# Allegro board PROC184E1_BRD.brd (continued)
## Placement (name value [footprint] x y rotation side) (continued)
R325  0E  [RES0402_0-5]  20.24 91.07 180 top
R326  0E  [RES0402_0-5]  22.35 91.07 180 top
R327  10K_1%  [RES0201_0-5]  55.1 90.96 0 top
R328  10K_1%  [RES0201_0-5]  55.1 89.95 0 top
R329  0E  [RES0402_0-5]  20.24 89.92 180 top
R330  0E  [RES0402_0-5]  22.35 89.92 180 top
R331  10K_1%  [RES0402_0-5]  101.01 89.75 270 top
R332  0E  [RES0201_0-5]  79.02 89.45 90 top
R333  0E  [RES0201_0-5]  81.99 89.45 90 top
R334  0E  [RES0201_0-5]  82.98 89.45 90 top
R335  0E  [RES0201_0-5]  83.98 89.45 90 top
R336  10K_1%  [RES0402_0-5]  99.42 89.43 0 top
R337  10K_1%  [RES0402_0-5]  73.41 89.36 180 top
R338  0.01E_1%  [RES_FC4L16_0306-4_0-7]  189.83 89.43 90 top
R339  10K_1%  [RES0201_0-5]  55.1 88.86 0 top
R340  0E  [RES0402_0-5]  20.24 88.78 180 top
R341  0E  [RES0402_0-5]  22.35 88.78 180 top
R342  1K_1%  [RES0402_0-5]  76.34 88.6 0 top
R343  0E  [RES0402_0-5]  7.37 88.3 180 top
R344  100E_1%  [RES0402_0-5]  87.52 88.19 0 top
R345  0E  [RES0201_0-5]  42.67 87.88 270 top
R346  22E_1%  [RES0402_0-5]  55.15 87.73 0 top
R347  0E  [RES0402_0-5]  20.24 87.64 180 top
R348  0E  [RES0402_0-5]  22.35 87.64 180 top
R349  100E_1%  [RES0402_0-5]  74.35 86.87 0 top
R350  0E  [RES0402_0-5]  7.37 87.15 180 top
R351  0.01E_1%  [RES_FC4L16_0306-4_0-7]  76.81 87.15 90 top
R352  0.01E_1%  [RES_FC4L16_0306-4_0-7]  169.6 87.03 270 top
R353  10K_1%  [RES0402_0-5]  97.34 86.65 0 top
R354  0E  [RES0402_0-5]  20.24 86.49 0 top
R355  10E_1%  [RES0402_0-5]  22.35 86.49 180 top
R356  100E_1%  [RES0402_0-5]  7.37 85.92 0 top
R357  0.01E_1%  [RES_KRL2012_0805-4_0-7_TI]  227.59 85.58 180 top
R358  10K_1%  [RES0402_0-5]  97.37 85.55 180 top
R359  10E_1%  [RES0402_0-5]  190.58 83.26 180 top
R360  4.7K  [RES0402_0-5]  20.24 85.35 180 top
R361  4.7K  [RES0402_0-5]  7.37 84.78 180 top
R362  0.01E_1%  [RES_FC4L16_0306-4_0-7]  183.68 84.71 0 top
R363  0E  [RES0201_0-5]  80.01 84.6 270 top
R364  0E  [RES0201_0-5]  81 84.6 270 top
R365  0E  [RES0201_0-5]  81.99 84.6 270 top
R366  0E  [RES0201_0-5]  82.98 84.6 270 top
R367  0E  [RES0201_0-5]  83.98 84.6 270 top
R368  0E  [RES0402_0-5]  101.2 68.44 180 top
R369  0.01E_1%  [RES_FC4L16_0306-4_0-7]  167.57 84.49 180 top
R370  10E_1%  [RES0402_0-5]  190.58 82.11 180 top
R371  0E  [RES0402_0-5]  20.24 84.21 180 top
R372  22E_1%  [RES0402_0-5]  22.35 84.21 180 top
R373  0E  [RES0402_0-5]  7.37 83.64 0 top
R374  10E_1%  [RES0402_0-5]  20.24 83.07 180 top
R375  10E_1%  [RES0402_0-5]  22.35 83.07 180 top
R376  0E  [RES0402_0-5]  7.37 82.49 0 top
R377  0.01E_1%  [RES_FC4L16_0306-4_0-7]  87.83 82.41 180 top
R378  0E  [RES0201_0-5]  165.12 82.39 0 top
R379  0E  [RES0402_0-5]  69.65 82.1 180 top
R380  100E_1%  [RES0402_0-5]  20.24 81.92 180 top
R381  4.7K  [RES0402_0-5]  22.35 81.92 0 top
R382  0.01E_1%  [RES_FC4L16_0306-4_0-7]  76.61 81.52 180 top
R383  22E_1%  [RES0402_0-5]  7.37 81.35 180 top
R384  0E  [RES0402_0-5]  69.65 81.06 180 top
R385  0E  [RES0402_0-5]  71.69 81.04 180 top
R387  100E_1%  [RES0402_0-5]  20.24 80.78 180 top
R388  10E_1%  [RES0402_0-5]  190.58 79.22 180 top
R389  22E_1%  [RES0402_0-5]  7.37 80.21 180 top
R392  0E  [RES0402_0-5]  74.13 79.82 180 top
R393  10E_1%  [RES0402_0-5]  190.58 78.08 180 top
R394  4.7K  [RES0402_0-5]  7.38 79.06 180 top
R395  0E  [RES0402_0-5]  116.16 60.29 270 top
R396  240E_1%  [RES0201_0-5]  165.12 78.84 0 top
R398  0E  [RES0402_0-5]  184.83 78.57 180 top
R399  0E  [RES0402_0-5]  115.76 60.7 180 top
R401  10K_1%  [RES0402_0-5]  80.97 77.8 0 top
R402  0E  [RES0402_0-5]  117.97 61.49 0 top
R403  10K_1%  [RES0402_0-5]  41.48 77.7 0 top
R404  0E  [RES0201_0-5]  165.12 76.8 0 top
R405  10K_1%  [RES0402_0-5]  41.5 76.51 180 top
R406  24.9K_1%  [RES0402_0-5]  82.77 76.46 0 top
R407  10K_1%  [RES0402_0-5]  85.35 76.5 90 top
R408  10E_1%  [RES0402_0-5]  190.58 75.19 180 top
R409  10K_1%  [RES0402_0-5]  75.5 75.85 0 top
R410  53.6K_1%  [RES0402_0-5]  81.15 75.83 270 top
R411  10K_1%  [RES0402_0-5]  41.47 75.19 0 top
R412  10E_1%  [RES0402_0-5]  190.58 74.05 180 top
R413  10K_1%  [RES0402_0-5]  75.5 74.58 180 top
R414  1K_1%  [RES0201_0-5]  65.04 73.13 180 top
R415  0.01E_1%  [RES_FC4L16_0306-4_0-7]  82.39 72.86 180 top
R416  0E  [RES0402_0-5]  66.76 72.71 90 top
R417  10K_1%  [RES0402_0-5]  73 72.4 180 top
R418  0.01E_1%  [RES_KRL2012_0805-4_0-7_TI]  232.34 72.17 270 top
R419  10K_1%  [RES0402_0-5]  63.15 72.12 180 top
R420  10K_1%  [RES0402_0-5]  65.13 72.12 180 top
R421  0E  [RES0402_0-5]  84.18 71.87 270 top
R422  10K_1%  [RES0402_0-5]  63.15 70.85 180 top
R423  10K_1%  [RES0402_0-5]  65.13 70.85 180 top
R424  0E  [RES0402_0-5]  82.64 70.67 0 top
R425  0E  [RES0402_0-5]  87.13 70.67 0 top
R426  0E  [RES0402_0-5]  89.02 70.67 180 top
R427  0.01E_1%  [RES_FC4L16_0306-4_0-7]  187.51 70.52 180 top
R428  1K_1%  [RES0201_0-5]  66.23 69.5 180 top
R429  0.01E_1%  [RES_FC4L16_0306-4_0-7]  166.71 69.19 0 top
R430  1K_1%  [RES0402_0-5]  46.31 68.18 0 top
R431  10K  [RES0402_0-5]  58.84 68.18 180 top
R432  0.01E_1%  [RES_FC4L16_0306-4_0-7]  85.66 67.97 180 top
R433  220E_1%  [RES0402_0-5]  187.26 67.5 180 top
R435  1K_1%  [RES0402_0-5]  46.31 66.91 0 top
R436  10K  [RES0402_0-5]  58.84 66.91 180 top
R437  10K_1%  [RES0402_0-5]  79.78 66.33 0 top
R438  0E  [RES0402_0-5]  86.88 65.98 270 top
R439  0.01E_1%  [RES_FC4L16_0306-4_0-7]  166.5 65.97 270 top
R440  240E  [RES0402_0-5]  91.41 65.82 180 top
R441  1K_1%  [RES0402_0-5]  46.31 65.64 0 top
R442  10K  [RES0402_0-5]  58.84 65.64 180 top
R443  10K  [RES0402_0-5]  189.54 65.45 270 top
R444  240E  [RES0402_0-5]  93.01 65.39 90 top
R445  2.2K  [RES0201_0-5]  28.57 65.39 270 top
R446  0E  [RES0402_0-5]  136.61 51.79 0 bottom
R447  10K_1%  [RES0402_0-5]  75.75 64.1 270 top
R448  10K_1%  [RES0402_0-5]  166.57 64.39 180 top
R449  0.008E_1%  [RES1206_0-75]  230.72 64.52 90 top
R450  1K_1%  [RES0402_0-5]  46.31 64.37 0 top
R451  10K  [RES0402_0-5]  58.84 64.37 180 top
R452  0E  [RES0402_0-5]  86.9 64.17 90 top
R453  10K  [RES0402_0-5]  194.62 63.33 0 top
R454  1K_1%  [RES0402_0-5]  46.31 63.1 0 top
R455  10K  [RES0402_0-5]  58.84 63.1 180 top
R456  2.2K  [RES0201_0-5]  25.89 63 90 top
R457  100K  [RES0402_0-5]  143.49 45.92 180 top
R458  0E  [RES0402_0-5]  129.93 62.03 270 top
R459  10K  [RES0402_0-5]  194.62 62.19 180 top
R460  1K_1%  [RES0402_0-5]  46.31 61.83 0 top
R461  10K  [RES0402_0-5]  58.84 61.83 180 top
R462  0E  [RES0402_0-5]  29.9 61.75 270 top
R463  2.2K  [RES0201_0-5]  25.89 61.37 270 top
R464  10E_1%  [RES0402_0-5]  209.06 61.17 180 top
R465  90.9K_1%  [RES0402_0-5]  202.26 61.11 270 top
R466  10K_1%  [RES0402_0-5]  203.49 61.11 90 top
R467  1K_1%  [RES0402_0-5]  46.31 60.56 0 top
R468  10K  [RES0402_0-5]  58.84 60.56 180 top
R469  10K  [RES0402_0-5]  187.33 60.12 270 top
R470  2.2K  [RES0201_0-5]  94.22 24.59 270 top
R471  0E  [RES0402_0-5]  197.25 59.78 180 top
R472  10K_1%  [RES0402_0-5]  191.87 99.63 270 top
R473  24.9K_1%  [RES0402_0-5]  202.47 59.42 180 top
R474  1K_1%  [RES0402_0-5]  46.31 59.29 0 top
R475  10K  [RES0402_0-5]  58.84 59.29 180 top
R476  10K_1%  [RES0402_0-5]  22.4 59.13 90 top
R477  0E  [RES0402_0-5]  127.08 63.6 0 top
R478  2.2K  [RES0201_0-5]  27.07 58.94 90 top
R479  10K_1%  [RES0402_0-5]  193.14 99.63 270 top
R481  10K  [RES0402_0-5]  202.19 55.35 180 top
R482  0E  [RES0402_0-5]  210.75 55.2 0 top
R483  1K_1%  [RES0402_0-5]  46.31 54.63 0 top
R484  10K  [RES0402_0-5]  58.84 54.63 180 top
R485  0.01E_1%  [RES_FC4L16_0306-4_0-7]  154.95 54.31 0 top
R486  5.36K_1%  [RES0402_0-5]  179.41 54.26 270 top
R487  0E  [RES0402_0-5]  180.87 54.97 270 top
R488  0E  [RES0402_0-5]  210.75 54.06 0 top
R489  10K_1%  [RES0402_0-5]  129.6 40.82 270 bottom
R490  10K_1%  [RES0402_0-5]  128.6 40.82 270 bottom
R491  10K_1%  [RES0402_0-5]  127.6 40.82 270 bottom
R492  44.2K_1%  [RES0402_0-5]  207.01 53.56 270 top
R493  10K_1%  [RES0402_0-5]  121.85 40.82 270 bottom
R494  10K_1%  [RES0402_0-5]  120.85 40.82 270 bottom
R495  10K_1%  [RES0402_0-5]  119.85 40.82 270 bottom
R496  1K_1%  [RES0402_0-5]  46.31 53.36 0 top
R497  10K  [RES0402_0-5]  58.84 53.36 180 top
R498  10K_1%  [RES0402_0-5]  200.1 100.31 90 top
R499  10K_1%  [RES0402_0-5]  198.83 100.31 90 top
R500  10K_1%  [RES0402_0-5]  125.6 38.98 90 bottom
R501  10K  [RES0402_0-5]  211.65 52.26 180 top
R502  1K_1%  [RES0402_0-5]  46.31 52.09 0 top
R503  10K  [RES0402_0-5]  58.84 52.09 180 top
R504  10K_1%  [RES0402_0-5]  166.28 52.05 0 top
R505  56.2K_1%  [RES0402_0-5]  156.52 51.85 90 top
R506  10K_1%  [RES0402_0-5]  129.02 39.4 180 bottom
R507  10K_1%  [RES0402_0-5]  121.85 38.82 270 bottom
R508  10K_1%  [RES0402_0-5]  119.85 38.82 270 bottom
R509  10E_1%  [RES0402_0-5]  187 51.51 180 top
R510  10K  [RES0402_0-5]  211.65 51.11 180 top
R511  10K_1%  [RES0402_0-5]  161.51 51.07 270 top
R512  0E  [RES0402_0-5]  166.3 50.96 0 top
R513  10K_1%  [RES0402_0-5]  126.6 39.82 270 bottom
R514  1K_1%  [RES0402_0-5]  46.31 50.82 0 top
R515  10K  [RES0402_0-5]  58.84 50.82 180 top
R516  10K_1%  [RES0402_0-5]  117.85 38.82 270 bottom
R517  10K_1%  [RES0402_0-5]  127.6 38.98 90 bottom
R518  10K_1%  [RES0402_0-5]  120.85 38.82 270 bottom
R519  10K_1%  [RES0402_0-5]  122.27 37.4 180 bottom
R520  10E_1%  [RES0402_0-5]  187 50.37 180 top
R521  24.9K_1%  [RES0402_0-5]  156.02 50.32 180 top
R522  200K  [RES0402_0-5]  203.16 50.32 270 top
R523  10K_1%  [RES0402_0-5]  126.6 37.98 90 bottom
R524  16.2K_1%  [RES0402_0-5]  166.3 49.87 0 top
R525  10K_1%  [RES0201_0-5]  129.93 37.4 0 bottom
R526  22E_1%  [RES0402_0-5]  128.18 37.4 180 bottom
R527  10K_1%  [RES0402_0-5]  118.43 37.4 0 bottom
R528  0E  [RES0402_0-5]  174.38 49.56 0 top
R529  1K_1%  [RES0402_0-5]  46.31 49.55 0 top
R530  10K  [RES0402_0-5]  58.84 49.55 180 top
R531  10K_1%  [RES0402_0-5]  173.06 49.19 90 top
R532  22E_1%  [RES0402_0-5]  120.99 36.81 270 bottom
R533  100K  [RES0402_0-5]  122.27 36.4 0 bottom
R534  10K_1%  [RES0402_0-5]  159.95 48.64 270 top
R536  1K_1%  [RES0402_0-5]  46.31 48.28 0 top
R537  10K  [RES0402_0-5]  58.84 48.28 180 top
R538  10K_1%  [RES0402_0-5]  182.89 48.19 270 top
R539  0E  [RES0402_0-5]  221.12 47.8 90 top
R540  100K  [RES0402_0-5]  121.41 35.42 0 bottom
R541  10K_1%  [RES0201_0-5]  125.27 35.4 180 bottom
R542  10K_1%  [RES0402_0-5]  128.18 35.4 180 bottom
R543  100K  [RES0402_0-5]  129.6 35.98 270 bottom
R544  49.9E_1%  [RES0402_0-5]  162.8 47.31 90 top
R545  10K_1%  [RES0402_0-5]  176.67 47.09 90 top
R546  0E  [RES0402_0-5]  178.82 47.05 270 top
R547  10K_1%  [RES0402_0-5]  181.29 53.42 0 top
R548  1K_1%  [RES0402_0-5]  46.31 47.01 0 top
R549  10K  [RES0402_0-5]  58.84 47.01 180 top
R550  10K_1%  [RES0201_0-5]  65.74 46.79 180 top
R551  10E_1%  [RES0402_0-5]  187 46.75 180 top
R552  1K_1%  [RES0402_0-5]  128.18 36.4 180 bottom
R553  1K_1%  [RES0402_0-5]  46.31 45.74 0 top
R554  10K  [RES0402_0-5]  58.84 45.74 180 top
R555  10E_1%  [RES0402_0-5]  187 45.61 180 top
R556  49.9E_1%  [RES0402_0-5]  78.55 45.43 90 top
R557  10K_1%  [RES0402_0-5]  159.21 43.39 180 top
R558  10E_1%  [RES0402_0-5]  187 42.56 180 top
R559  0E  [RES0402_0-5]  51.77 42.54 270 top
R560  4.7K  [RES0402_0-5]  59.67 42.2 0 top
R561  10K  [RES0402_0-5]  74.5 41.83 180 top
R562  10E_1%  [RES0402_0-5]  187 41.42 180 top
R563  10K  [RES0402_0-5]  90.48 41.36 90 top
R564  10K_1%  [RES0402_0-5]  53.78 40.8 0 top
R565  0E  [RES0402_0-5]  51.77 40.63 90 top
R566  1M_1%  [RES0402_0-5]  79.79 40.6 180 top
R567  10K  [RES0402_0-5]  74.5 40.56 0 top
R568  0E  [RES0402_0-5]  228.74 40.47 180 top
R569  10K_1%  [RES0402_0-5]  79.79 39.45 0 top
R570  10E_1%  [RES0402_0-5]  169.26 39.25 90 top
R571  10E_1%  [RES0402_0-5]  170.4 39.25 90 top
R572  10E_1%  [RES0402_0-5]  173.58 39.25 90 top
R573  10E_1%  [RES0402_0-5]  174.72 39.25 90 top
R574  10E_1%  [RES0402_0-5]  177.89 39.25 90 top
R575  10E_1%  [RES0402_0-5]  179.04 39.25 90 top
R576  0E  [RES0402_0-5]  30.32 38.82 180 top
R577  0E  [RES0402_0-5]  31.16 38.82 0 top
R578  1K_1%  [RES0402_0-5]  227.76 38.38 90 top
R579  10E_1%  [RES0402_0-5]  187 38.37 180 top
R580  49.9E_1%  [RES0402_0-5]  158.7 38.22 270 top
R581  0E  [RES0402_0-5]  30.34 37.45 180 top
R582  0E  [RES0402_0-5]  31.18 37.45 0 top
R583  10E_1%  [RES0402_0-5]  187 37.23 180 top
R584  10K_1%  [RES0402_0-5]  79.79 36.79 0 top
R585  1K_1%  [RES0402_0-5]  223.18 35.25 180 top
R586  10K  [RES0402_0-5]  86.1 35.14 270 top
R587  10K  [RES0402_0-5]  87.37 35.14 90 top
R588  0E  [RES0402_0-5]  166.68 34.92 0 top
R589  10K  [RES0402_0-5]  224.85 34.83 90 top
R590  10K  [RES0402_0-5]  230.11 34.75 0 top
R591  10K  [RES0402_0-5]  159.57 34.45 180 top
R592  10E_1%  [RES0402_0-5]  187 34.18 180 top
R593  10K  [RES0402_0-5]  166.68 33.65 180 top
R594  10E_1%  [RES0402_0-5]  153.52 33.6 90 top
R595  10E_1%  [RES0402_0-5]  154.66 33.6 90 top
R596  10K  [RES0402_0-5]  22.65 33.45 180 top
R597  100K  [RES0402_0-5]  24.63 33.45 0 top
R598  10K  [RES0402_0-5]  26.8 33.45 0 top
R599  100K  [RES0402_0-5]  28.75 33.45 180 top
R600  0E  [RES0402_0-5]  157.92 33.36 270 top
R601  10E_1%  [RES0402_0-5]  187 33.04 180 top
R602  0E  [RES0402_0-5]  22.65 32.18 0 top
R603  0E  [RES0402_0-5]  24.63 32.18 0 top
R604  0E  [RES0402_0-5]  26.8 32.18 180 top
R605  0E  [RES0402_0-5]  28.75 32.18 180 top
R606  0E  [RES0402_0-5]  226.37 31.57 90 top
R607  4.53K_1%  [RES0402_0-5]  113.34 31.53 90 top
R608  4.7K  [RES0402_0-5]  50.54 31.31 0 top
R609  10K  [RES0402_0-5]  52.53 31.31 180 top
R610  10K  [RES0402_0-5]  54.35 31.31 180 top
R611  1.13K_1%  [RES0402_0-5]  111.82 31.27 0 top
R612  10K  [RES0402_0-5]  226.79 30 0 top
R613  0E  [RES0402_0-5]  136.01 29.52 0 top
R614  10K  [RES0402_0-5]  160.28 29.47 0 top
R615  10K_1%  [RES0402_0-5]  158.05 29.41 180 top
R616  10K  [RES0402_0-5]  54.76 29.37 0 top
R617  3K_1%  [RES0402_0-5]  31.17 29.26 270 top
R618  0E  [RES0402_0-5]  160.28 28.33 180 top
R619  10K_1%  [RES0402_0-5]  136.01 28.25 0 top
R620  523K_1%  [RES0402_0-5]  158.47 27.85 90 top
R621  2.49K_1%  [RES0402_0-5]  79.64 27.77 0 top
R622  2.49K_1%  [RES0402_0-5]  105.29 27.77 0 top
R623  10K  [RES0402_0-5]  225.36 27.32 180 top
R624  10K_1%  [RES0402_0-5]  137.58 27.18 90 top
R625  47E  [RES0402_0-5]  35.72 27.15 0 top
R626  0E  [RES0402_0-5]  136.01 26.98 0 top
R627  10K_1%  [RES0402_0-5]  128.57 26.93 0 top
R628  10K  [RES0402_0-5]  49.78 26.79 270 top
R629  5.76K_1%  [RES0402_0-5]  79.64 26.63 180 top
R630  5.76K_1%  [RES0402_0-5]  105.29 26.63 180 top
R631  1K_1%  [RES0402_0-5]  160.21 26.18 0 top
R632  1.5K_1%  [RES0402_0-5]  35.72 26.11 0 top
R633  0E  [RES0402_0-5]  20.97 25.34 180 top
R634  49.9E_1%  [RES0402_0-5]  23.92 25.34 180 top
R635  100K  [RES0402_0-5]  200.72 25.09 0 top
R636  1.5K_1%  [RES0402_0-5]  35.72 25.07 0 top
R637  100K  [RES0402_0-5]  22.44 24.92 90 top
R638  10K  [RES0402_0-5]  51.8 24.75 270 top
R639  10K  [RES0402_0-5]  119.53 24.59 180 top
R640  150K_1%  [RES0402_0-5]  26.53 24.5 0 top
R641  1.69K_1%  [RES0402_0-5]  113.34 24.09 90 top
R642  1.5K_1%  [RES0402_0-5]  35.01 23.94 0 top
R643  3.57K_1%  [RES0402_0-5]  111.82 23.83 0 top
R644  0E  [RES0402_0-5]  18.46 23.83 270 top
R645  0E  [RES0402_0-5]  123.66 23.22 90 top
R646  0E  [RES0402_0-5]  124.93 23.22 90 top
R647  10K_1%  [RES0402_0-5]  126.2 23.22 270 top
R648  10K  [RES0402_0-5]  119.74 23.2 180 top
R649  10K_1%  [RES0402_0-5]  79.64 23.13 180 top
R650  10K_1%  [RES0402_0-5]  105.29 23.13 180 top
R651  47E  [RES0402_0-5]  35.01 22.8 0 top
R652  10K_1%  [RES0402_0-5]  226.02 22.23 0 top
R653  1K_1%  [RES0402_0-5]  237.78 22.21 0 top
R654  2.49K_1%  [RES0402_0-5]  79.64 22.11 0 top
R655  2.49K_1%  [RES0402_0-5]  105.29 22.11 0 top
R656  0E  [RES0402_0-5]  18.46 21.8 270 top
R657  5.9K_1%  [RES0402_0-5]  19.6 21.8 270 top
R658  0E  [RES0402_0-5]  126.95 21.24 270 top
R659  10K_1%  [RES0402_0-5]  128.22 21.24 90 top
R660  10K_1%  [RES0402_0-5]  225.99 20.99 0 top
R661  1K_1%  [RES0402_0-5]  237.78 20.96 0 top
R662  10K_1%  [RES0402_0-5]  171.96 20.24 0 top
R663  10K_1%  [RES0402_0-5]  225.99 19.72 0 top
R664  1K_1%  [RES0402_0-5]  237.78 19.69 0 top
R665  0E  [RES0402_0-5]  18.46 19.64 90 top
R666  5.9K_1%  [RES0402_0-5]  19.6 19.64 90 top
R667  10K  [RES0402_0-5]  179.64 9.96 270 top
R668  2.2K  [RES0402_0-5]  178.37 9.96 90 top
R669  10K  [RES0402_0-5]  177.1 9.96 270 top
R670  10K  [RES0402_0-5]  175.83 9.96 270 top
R671  10K  [RES0402_0-5]  141.89 19.03 0 top
R672  1.5K_1%  [RES0402_0-5]  36.84 18.85 0 top
R673  1K_1%  [RES0402_0-5]  237.78 18.42 0 top
R674  1.5K_1%  [RES0402_0-5]  35.01 17.93 0 top
R675  0E  [RES0402_0-5]  18.46 17.61 90 top
R676  100K  [RES0402_0-5]  115.25 17.27 270 top
R677  33E_1%  [RES0402_0-5]  119.06 17.04 270 top
R678  150K_1%  [RES0402_0-5]  25.87 17 0 top
R679  33E_1%  [RES0402_0-5]  128.71 16.92 270 top
R680  33E_1%  [RES0402_0-5]  138.51 16.92 270 top
R681  33E_1%  [RES0402_0-5]  148.32 16.92 270 top
R682  33E_1%  [RES0402_0-5]  158.12 16.92 270 top
R683  33E_1%  [RES0402_0-5]  167.93 16.92 270 top
R684  330K_1%  [RES0402_0-5]  113.6 16.85 180 top
R685  47E  [RES0402_0-5]  35.04 16.82 0 top
R686  100K  [RES0402_0-5]  22.44 16.52 270 top
R687  0E  [RES0402_0-5]  54.42 16.4 90 top
R688  220K_1%  [RES0402_0-5]  55.69 16.4 270 top
R689  0E  [RES0402_0-5]  20.97 16.1 180 top
R690  49.9E_1%  [RES0402_0-5]  23.92 16.1 180 top
R691  47E  [RES0402_0-5]  35.7 15.34 0 top
R692  1.5K_1%  [RES0402_0-5]  35.7 14.3 0 top
R693  10K  [RES0402_0-5]  56.22 13.9 0 top
R694  10K  [RES0402_0-5]  58.12 13.9 0 top
R695  10K  [RES0402_0-5]  38.37 12.99 0 top
R696  1M_1%  [RES0805_0-75]  88.93 12.86 270 top
R697  1M_1%  [RES0805_0-75]  63.84 12.76 270 top
R698  10K  [RES0402_0-5]  56.22 12.38 0 top
R699  10K  [RES0402_0-5]  58.12 12.38 0 top
R700  3K_1%  [RES0402_0-5]  29.85 12.17 0 top
R701  10K  [RES0402_0-5]  194.75 11.6 0 top
R702  10K  [RES0402_0-5]  220.85 11.6 0 top
R703  12K_1%  [RES0402_0-5]  189.04 11.22 90 top
R704  12K_1%  [RES0402_0-5]  215.14 11.22 90 top
R705  22E_1%  [RES0402_0-5]  37.65 11.21 180 top
R706  10K  [RES0402_0-5]  134.45 10.7 0 top
R707  10K  [RES0402_0-5]  144.26 10.7 0 top
R708  10K  [RES0402_0-5]  154.06 10.7 0 top
R709  10K  [RES0402_0-5]  163.86 10.7 0 top
R710  10K_1%  [RES0402_0-5]  173.67 10.7 180 top
R711  59E_1%  [RES0402_0-5]  119.91 7.57 0 top
R712  59E_1%  [RES0402_0-5]  122.02 7.57 0 top
R713  59E_1%  [RES0402_0-5]  129.56 7.38 0 top
R714  59E_1%  [RES0402_0-5]  131.67 7.38 0 top
R715  59E_1%  [RES0402_0-5]  139.36 7.38 0 top
R716  59E_1%  [RES0402_0-5]  141.47 7.38 0 top
R717  59E_1%  [RES0402_0-5]  149.17 7.38 0 top
R718  59E_1%  [RES0402_0-5]  151.28 7.38 0 top
R719  59E_1%  [RES0402_0-5]  158.97 7.38 0 top
R720  59E_1%  [RES0402_0-5]  161.08 7.38 0 top
R721  59E_1%  [RES0402_0-5]  168.78 7.38 0 top
R722  59E_1%  [RES0402_0-5]  170.89 7.38 0 top
R723  33.2K_1%  [RES0402_0-5]  115.5 7.24 90 top
R724  3.32K_1%  [RES0402_0-5]  116.65 7.24 270 top
R725  220E_1%  [RES0402_0-5]  197.02 6.96 180 top
R726  0E  [RES0402_0-5]  114.23 6.13 90 top
R727  220E_1%  [RES0402_0-5]  218.53 4.8 180 top
R728  0E  [RES0805_0-75]  181.32 3.16 180 top
R729  0E  [RES0805_0-75]  201.46 3.16 180 top
R730  1M_1%  [RES0805_0-75]  157.59 188.55 180 bottom
R731  499K_1%  [RES0402_0-5]  183.12 186.6 0 bottom
R732  910K  [RES0402_0-5]  184.84 184.06 0 bottom
R734  10K  [RES0402_0-5]  178.88 183.67 180 bottom
R735  100E_1%  [RES0402_0-5]  15.17 183.55 90 bottom
R736  10K  [RES0402_0-5]  14.03 183.55 270 bottom
R737  1M_1%  [RES0805_0-75]  33.51 183.07 0 bottom
R738  2.2K  [RES0201_0-5]  7.47 138.82 90 top
R739  200K  [RES0402_0-5]  184.84 182.91 180 bottom
R740  0E  [RES0402_0-5]  58.17 182.56 0 bottom
R741  10K  [RES0402_0-5]  13.39 182.02 180 bottom
R742  2.2K  [RES0201_0-5]  9.09 139.15 0 top
R743  200K  [RES0402_0-5]  183.39 181.34 270 bottom
R744  200K  [RES0402_0-5]  181.99 181.34 90 bottom
R745  5.1K_1%  [RES0402_0-5]  180.59 181.34 270 bottom
R746  10K  [RES0402_0-5]  176.6 180.31 270 bottom
R747  100K  [RES0402_0-5]  175.48 180.27 90 bottom
R748  100K  [RES0402_0-5]  174.34 180.27 90 bottom
R749  100E_1%  [RES0402_0-5]  25.45 180.21 90 bottom
R750  0E  [RES0402_0-5]  23.16 180.21 90 bottom
R751  51E  [RES0402_0-5]  9.44 179.96 0 bottom
R752  0E  [RES0402_0-5]  177.88 179.92 270 bottom
R753  200K  [RES0402_0-5]  182.58 179.86 0 bottom
R754  0E  [RES0402_0-5]  122.38 179.23 0 bottom
R755  0E  [RES0402_0-5]  96.51 179.23 0 bottom
R756  1K_1%  [RES0402_0-5]  6.92 178.72 0 bottom
R757  0E  [RES0402_0-5]  122.38 177.96 0 bottom
R758  0E  [RES0402_0-5]  96.51 177.96 0 bottom
R759  100K  [RES0402_0-5]  124.22 177.95 180 bottom
R760  100K  [RES0402_0-5]  98.31 177.81 180 bottom
R761  1K_1%  [RES0402_0-5]  6.92 177.58 180 bottom
R762  1K_1%  [RES0402_0-5]  6.92 176.44 0 bottom
R763  0E  [RES0402_0-5]  157.74 176.25 180 bottom
R764  10K  [RES0402_0-5]  155.81 176.25 180 bottom
R765  10K  [RES0402_0-5]  62.9 176.15 180 bottom
R766  3.57K_1%  [RES0402_0-5]  106.1 175.42 270 bottom
R767  1K_1%  [RES0402_0-5]  6.92 175.29 180 bottom
R768  1K_1%  [RES0402_0-5]  6.92 174.15 180 bottom
R769  1.15K_1%  [RES0402_0-5]  105.85 173.9 180 bottom
R770  1K_1%  [RES0402_0-5]  6.92 173.01 0 bottom
R771  10K  [RES0402_0-5]  155.68 172.83 180 bottom
R772  0E  [RES0402_0-5]  59.42 172.13 0 bottom
R773  10K  [RES0402_0-5]  155.68 171.69 180 bottom
R774  0E  [RES0402_0-5]  139.39 171.66 90 bottom
R775  0E  [RES0402_0-5]  138.24 171.66 90 bottom
R776  51K  [RES0402_0-5]  98.24 171.31 90 bottom
R777  0E  [RES0201_0-5]  162.78 171.07 270 bottom
R778  0E  [RES0201_0-5]  161.77 171.07 270 bottom
R779  10K  [RES0402_0-5]  31.81 170.92 0 bottom
R780  10K_1%  [RES0402_0-5]  237.39 170.2 90 bottom
R781  4.7K  [RES0402_0-5]  59.42 169.68 180 bottom
R782  10K  [RES0402_0-5]  33.35 169.65 0 bottom
R783  10K  [RES0402_0-5]  163.63 169.03 180 bottom
R784  10K  [RES0402_0-5]  7.04 168.43 180 bottom
R785  10K_1%  [RES0402_0-5]  150.84 168.23 0 bottom
R786  10K  [RES0402_0-5]  104.81 167.9 270 bottom
R787  4.7K  [RES0402_0-5]  59.42 167.39 180 bottom
R788  0E  [RES0402_0-5]  164.51 167.32 180 bottom
R789  10K  [RES0402_0-5]  7.04 167.29 180 bottom
R790  10K_1%  [RES0402_0-5]  151.68 166.96 0 bottom
R791  3.57K_1%  [RES0402_0-5]  127.06 166.78 0 bottom
R792  0E  [RES0402_0-5]  162.89 166.73 270 bottom
R793  1.15K_1%  [RES0402_0-5]  128.58 166.36 270 bottom
R794  0E  [RES0402_0-5]  164.51 166.18 180 bottom
R795  0E  [RES0402_0-5]  138.88 165.95 270 bottom
R796  0E  [RES0402_0-5]  137.74 165.95 270 bottom
R797  10E_1%  [RES0402_0-5]  151.68 165.66 180 bottom
R798  10K  [RES0402_0-5]  134.58 165.49 0 bottom
R799  10K_1%  [RES0402_0-5]  141.65 165.32 180 bottom
R800  10E_1%  [RES0402_0-5]  189.32 164.57 270 bottom
R801  10E_1%  [RES0402_0-5]  188.18 164.57 270 bottom
R802  10K  [RES0402_0-5]  31.01 164.16 180 bottom
R803  10K_1%  [RES0402_0-5]  141.65 163.93 180 bottom
R804  10K_1%  [RES0402_0-5]  151.89 163.88 0 bottom
R805  10K_1%  [RES0402_0-5]  155.49 163.59 0 bottom
R806  9.09K_1%  [RES0402_0-5]  151.89 162.77 180 bottom
R807  10K_1%  [RES0402_0-5]  141.65 162.66 180 bottom
R808  4.7K  [RES0402_0-5]  111.07 162.61 180 bottom
R809  2.2K  [RES0201_0-5]  128.47 161.87 270 bottom
R810  2.2K  [RES0201_0-5]  129.69 161.44 270 bottom
R811  0E  [RES0402_0-5]  18.13 159.01 0 bottom
R812  0E  [RES0402_0-5]  16.45 158.59 270 bottom
R813  0E  [RES0402_0-5]  17.71 157.39 270 bottom
R814  0E  [RES0402_0-5]  17.71 155.49 90 bottom
R815  10K  [RES0402_0-5]  16.57 155.49 90 bottom
R816  0E  [RES0402_0-5]  203.64 155.29 90 bottom
R817  10K  [RES0402_0-5]  202.28 154.66 90 bottom
R818  0E  [RES0402_0-5]  52.02 150.29 270 bottom
R819  10K  [RES0402_0-5]  21.36 149.99 270 bottom
R820  10K  [RES0402_0-5]  20.21 149.99 90 bottom
R821  10K  [RES0402_0-5]  19.07 149.99 90 bottom
R822  10K  [RES0402_0-5]  17.93 149.99 270 bottom
R823  10K  [RES0402_0-5]  33.02 149.92 90 bottom
R824  10K  [RES0402_0-5]  30.29 149.92 270 bottom
R825  0E  [RES0402_0-5]  29.02 149.92 90 bottom
R826  10K  [RES0402_0-5]  16.72 147.89 0 bottom
R827  10K  [RES0402_0-5]  16.72 146.74 0 bottom
R828  10K  [RES0402_0-5]  202.46 146.1 270 bottom
R829  0E  [RES0402_0-5]  211.13 145.07 270 bottom
R830  100K  [RES0402_0-5]  209.86 145.07 90 bottom
R831  10K  [RES0402_0-5]  208.59 145.07 90 bottom
R832  0E  [RES0402_0-5]  206.3 144.52 90 bottom
R833  10K  [RES0402_0-5]  205.04 144.51 90 bottom
R834  45K_1%  [RES0402_0-5]  203.77 144.51 90 bottom
R845  10K  [RES0402_0-5]  207.2 139.99 180 bottom
R846  9.09K_1%  [RES0402_0-5]  212.66 139.35 90 bottom
R847  715K_1%  [RES0402_0-5]  207.2 138.72 0 bottom
R848  0E  [RES0402_0-5]  17.97 137.45 270 bottom
R849  90.9K_1%  [RES0402_0-5]  207.2 137.45 180 bottom
R850  715K_1%  [RES0402_0-5]  209.48 135.8 90 bottom
R851  24.9K_1%  [RES0402_0-5]  208.21 135.8 270 bottom
R853  0E  [RES0402_0-5]  17.97 135.55 90 bottom
R854  10K  [RES0402_0-5]  16.82 135.55 90 bottom
R857  10K_1%  [RES0402_0-5]  114.8 133.82 90 bottom
R858  0E  [RES0402_0-5]  117.68 132.68 180 bottom
R859  0E  [RES0201_0-5]  138.3 132.59 90 bottom
R860  0E  [RES0201_0-5]  137.28 132.59 90 bottom
R861  49.9E_1%  [RES0402_0-5]  138.72 131.22 0 bottom
R862  49.9E_1%  [RES0402_0-5]  136.86 131.22 180 bottom
R863  10K  [RES0402_0-5]  84.08 130.97 0 bottom
R864  10K_1%  [RES0402_0-5]  115.65 130.92 0 bottom
R865  4.99K_1%  [RES0402_0-5]  90.25 130.21 90 bottom
R866  2.49K_1%  [RES0402_0-5]  91.78 129.95 180 bottom
R867  0E  [RES0201_0-5]  129.91 129.91 90 bottom
R868  0E  [RES0201_0-5]  130.93 129.91 90 bottom
R869  0E  [RES0201_0-5]  138.3 129.9 270 bottom
R870  0E  [RES0201_0-5]  137.28 129.9 270 bottom
R871  10K  [RES0402_0-5]  33.02 129.85 90 bottom
R872  0E  [RES0402_0-5]  29.02 129.85 90 bottom
R873  10K  [RES0402_0-5]  25.65 129.85 270 bottom
R874  10K_1%  [RES0402_0-5]  115.65 129.78 0 bottom
R875  10K  [RES0402_0-5]  83.6 129.55 0 bottom
R876  0E  [RES0201_0-5]  129.91 129.25 270 bottom
R877  0E  [RES0201_0-5]  130.93 129.25 270 bottom
R878  0E  [RES0402_0-5]  51.93 128.88 270 bottom
R879  0E  [RES0402_0-5]  50.95 128.87 90 bottom
R880  10K_1%  [RES0402_0-5]  118.7 128.63 0 bottom
R881  0E  [RES0402_0-5]  116.67 128.63 0 bottom
R882  0E  [RES0402_0-5]  38.02 128.39 90 bottom
R883  10K_1%  [RES0402_0-5]  118.7 127.49 180 bottom
R884  10K_1%  [RES0402_0-5]  116.67 127.49 180 bottom
R885  0E  [RES0201_0-5]  131.6 126.9 270 bottom
R886  0E  [RES0201_0-5]  132.61 126.9 270 bottom
R887  10E_1%  [RES0402_0-5]  152.01 126.52 270 bottom
R888  10E_1%  [RES0402_0-5]  150.87 126.52 270 bottom
R889  10K_1%  [RES0402_0-5]  118.7 126.35 180 bottom
R890  10K_1%  [RES0402_0-5]  116.67 126.35 180 bottom
R891  0E  [RES0201_0-5]  131.6 126.24 90 bottom
R892  0E  [RES0201_0-5]  132.61 126.24 90 bottom
R893  10K_1%  [RES0402_0-5]  118.7 125.2 180 bottom
R894  10K_1%  [RES0402_0-5]  116.67 125.2 180 bottom
R895  49.9E_1%  [RES0402_0-5]  138.59 125.19 0 bottom
R896  49.9E_1%  [RES0402_0-5]  136.61 125.19 180 bottom
R897  0E  [RES0402_0-5]  116.67 124.06 180 bottom
R898  10E_1%  [RES0402_0-5]  64.62 123.94 0 bottom
R899  0E  [RES0201_0-5]  138.17 123.43 90 bottom
R900  0E  [RES0201_0-5]  137.03 123.43 90 bottom
R901  10K  [RES0402_0-5]  45.73 123.05 90 bottom
R902  10K  [RES0402_0-5]  44.46 123.05 270 bottom
R903  10K  [RES0402_0-5]  27.03 123.05 270 bottom
R904  10E_1%  [RES0402_0-5]  64.62 122.79 0 bottom
R905  0E  [RES0201_0-5]  138.17 122.77 270 bottom
R906  0E  [RES0201_0-5]  137.03 122.77 270 bottom
R907  1K_1%  [RES0402_0-5]  173.9 122.38 90 bottom
R908  10K_1%  [RES0402_0-5]  172.73 121.54 270 bottom
R909  10E_1%  [RES0402_0-5]  92.24 122.42 0 bottom
R910  10E_1%  [RES0402_0-5]  92.24 121.28 0 bottom
R911  10E_1%  [RES0402_0-5]  157.66 120.96 0 bottom
R912  10K  [RES0402_0-5]  51.21 120.71 270 bottom
R913  10K_1%  [RES0402_0-5]  113.06 120.43 90 bottom
R914  12K_1%  [RES0402_0-5]  111.8 120.43 270 bottom
R915  10K_1%  [RES0402_0-5]  114.18 120.4 270 bottom
R916  47K  [RES0402_0-5]  27.64 120.39 180 bottom
R917  4.7K  [RES0402_0-5]  62.24 119.97 0 bottom
R918  499E_0.1%  [RES0402_0-5]  92.25 120.36 0 bottom
R919  10E_1%  [RES0402_0-5]  157.66 119.82 0 bottom
R920  4.7K  [RES0402_0-5]  57.82 119.27 270 bottom
R921  4.7K  [RES0402_0-5]  62.24 118.7 180 bottom
R922  47K  [RES0402_0-5]  27.22 118.64 270 bottom
R923  0.01E_1%  [RES_FC4L16_0306-4_0-7]  122.17 117.89 180 bottom
R924  0E  [RES0402_0-5]  120.11 117.72 180 bottom
R925  10E_1%  [RES0402_0-5]  92.49 117.39 0 bottom
R926  2.2K  [RES0201_0-5]  88.17 90.8 270 top
R927  10E_1%  [RES0402_0-5]  66.94 116.47 90 bottom
R928  10E_1%  [RES0402_0-5]  65.79 116.47 90 bottom
R929  10E_1%  [RES0402_0-5]  92.49 116.25 0 bottom
R930  0E  [RES0402_0-5]  120.53 116.1 270 bottom
R931  0E  [RES0402_0-5]  61.21 116.09 90 bottom
R932  10K_1%  [RES0402_0-5]  114.13 115.45 90 bottom
R933  100E_1%  [RES0402_0-5]  87.5 89.47 0 top
R934  47K  [RES0402_0-5]  29.38 115.18 90 bottom
R935  100E_1%  [RES0402_0-5]  74.77 88.28 270 top
R936  47K  [RES0402_0-5]  28.02 113.53 180 bottom
R937  47K  [RES0402_0-5]  28.02 111.91 180 bottom
R938  3.01K_1%  [RES0201_0-5]  120.2 113.29 90 bottom
R939  10K  [RES0402_0-5]  217.95 109.65 0 bottom
R940  10.5E_1%  [RES0402_0-5]  221.32 107.86 270 bottom
R941  10K_1%  [RES0402_0-5]  42.35 106.09 270 bottom
R944  4.7K  [RES0402_0-5]  20.1 104.18 0 bottom
R945  3.01K_1%  [RES0201_0-5]  165.9 104.12 0 bottom
R946  240E_1%  [RES0201_0-5]  164.29 104.12 0 bottom
R947  3.01K_1%  [RES0201_0-5]  162.64 104.12 0 bottom
R948  10K_1%  [RES0402_0-5]  160.87 104.12 0 bottom
R949  0E  [RES0402_0-5]  30.12 103.95 0 bottom
R950  10.5E_1%  [RES0402_0-5]  221.27 101.81 270 bottom
R951  4.7K  [RES0402_0-5]  26.86 100.3 0 bottom
R952  10K  [RES0402_0-5]  22.42 100.3 180 bottom
R953  10K  [RES0402_0-5]  20.51 100.3 180 bottom
R954  0E  [RES0402_0-5]  31.17 99.45 0 bottom
R955  0E  [RES0402_0-5]  30.33 99.45 180 bottom
R956  10K  [RES0402_0-5]  217.3 98.77 0 bottom
R957  0E  [RES0201_0-5]  47.58 98.27 0 bottom
R958  0E  [RES0402_0-5]  31.17 97.92 0 bottom
R959  0E  [RES0402_0-5]  30.33 97.92 180 bottom
R960  0E  [RES0402_0-5]  180.01 97.61 90 bottom
R961  49.9K_1%  [RES0402_0-5]  177.36 97.61 180 bottom
R962  0E  [RES0201_0-5]  47.58 97.48 0 bottom
R963  0E  [RES0201_0-5]  47.58 96.74 0 bottom
R964  0E  [RES0402_0-5]  183.13 96.12 180 bottom
R965  10K_1%  [RES0402_0-5]  157.59 89.81 270 bottom
R966  49.9K_1%  [RES0402_0-5]  176.08 95.79 90 bottom
R967  0E  [RES0402_0-5]  174.81 95.21 90 bottom
R968  10E_1%  [RES0402_0-5]  197.71 94.6 270 bottom
R969  10E_1%  [RES0402_0-5]  196.56 94.6 270 bottom
R970  10K_1%  [RES0402_0-5]  159.9 94.47 90 bottom
R971  10E_1%  [RES0402_0-5]  192.87 94.34 270 bottom
R972  10E_1%  [RES0402_0-5]  191.73 94.34 270 bottom
R973  10E_1%  [RES0402_0-5]  190.58 83.13 180 bottom
R974  10E_1%  [RES0402_0-5]  190.58 84.27 180 bottom
R975  10E_1%  [RES0402_0-5]  69.58 94.15 0 bottom
R976  10K  [RES0402_0-5]  175.23 93.58 180 bottom
R977  10E_1%  [RES0402_0-5]  69.58 93.01 0 bottom
R978  10K_1%  [RES0402_0-5]  159.9 92.57 90 bottom
R979  499E_0.1%  [RES0402_0-5]  91.06 89.11 90 bottom
R981  499E_0.1%  [RES0402_0-5]  92.59 88.41 180 bottom
R982  10K_1%  [RES0402_0-5]  174.51 89.61 90 bottom
R983  10E_1%  [RES0402_0-5]  69.58 89.1 0 bottom
R984  499E_0.1%  [RES0402_0-5]  92.59 87.26 180 bottom
R985  0E  [RES0201_0-5]  83.98 88.51 90 bottom
R986  0E  [RES0201_0-5]  82.98 88.51 90 bottom
R987  0E  [RES0201_0-5]  81.99 88.51 90 bottom
R988  0E  [RES0201_0-5]  81 88.51 90 bottom
R989  0E  [RES0201_0-5]  80.01 88.51 90 bottom
R990  0E  [RES0201_0-5]  79.02 88.51 90 bottom
R991  10E_1%  [RES0402_0-5]  69.58 87.96 0 bottom
R992  0E  [RES0201_0-5]  83.98 87.85 270 bottom
R993  0E  [RES0201_0-5]  82.98 87.85 270 bottom
R994  0E  [RES0201_0-5]  81.99 87.85 270 bottom
R995  0E  [RES0201_0-5]  81 87.85 270 bottom
R996  0E  [RES0201_0-5]  80.01 87.85 270 bottom
R997  0E  [RES0201_0-5]  79.02 87.85 270 bottom
R998  10K_1%  [RES0402_0-5]  159.92 87.41 90 bottom
R999  10K_1%  [RES0402_0-5]  26.46 86.9 0 bottom
R1000  0E  [RES0201_0-5]  83.98 86.23 90 bottom
R1001  0E  [RES0201_0-5]  82.98 86.23 90 bottom
R1002  0E  [RES0201_0-5]  81.99 86.23 90 bottom
R1003  0E  [RES0201_0-5]  81 86.23 90 bottom
R1004  0E  [RES0201_0-5]  80.01 86.23 90 bottom
R1005  0E  [RES0201_0-5]  79.02 86.23 90 bottom
R1006  0E  [RES0201_0-5]  83.98 85.57 270 bottom
R1007  0E  [RES0201_0-5]  82.98 85.57 270 bottom
R1008  0E  [RES0201_0-5]  81.99 85.57 270 bottom
R1009  0E  [RES0201_0-5]  81 85.57 270 bottom
R1010  0E  [RES0201_0-5]  80.01 85.57 270 bottom
R1011  0E  [RES0201_0-5]  79.02 85.57 270 bottom
R1012  10K_1%  [RES0402_0-5]  159.92 85.51 90 bottom
R1013  10E_1%  [RES0402_0-5]  69.58 84.05 0 bottom
R1014  0.01E_1%  [RES_FC4L16_0306-4_0-7]  77.46 83.7 270 bottom
R1015  10E_1%  [RES0402_0-5]  69.58 82.91 0 bottom
R1016  0E  [RES0603_0-75]  98.87 82.84 180 bottom
R1017  10K_1%  [RES0402_0-5]  27.86 82.84 180 bottom
R1018  499E_0.1%  [RES0402_0-5]  87.44 85.57 270 bottom
R1019  240E_1%  [RES0201_0-5]  151.57 82.2 90 bottom
R1020  240E_1%  [RES0201_0-5]  150.55 82.16 90 bottom
R1021  10E_1%  [RES0402_0-5]  228.28 81.8 180 bottom
R1022  0E  [RES0201_0-5]  111.31 70.87 315 bottom
R1023  0E  [RES0201_0-5]  109.25 62.43 270 bottom
R1024  10E_1%  [RES0402_0-5]  228.28 80.65 180 bottom
R1025  10K_1%  [RES0402_0-5]  24.74 80.42 270 bottom
R1026  0E  [RES0402_0-5]  178.21 79.14 180 bottom
R1027  0E  [RES0201_0-5]  112.5 69.62 135 bottom
R1028  0E  [RES0402_0-5]  21.56 79.02 270 bottom
R1029  10K_1%  [RES0402_0-5]  20.29 79.02 270 bottom
R1030  10K_1%  [RES0402_0-5]  18.79 79.02 270 bottom
R1031  10E_1%  [RES0402_0-5]  69.58 79 0 bottom
R1032  10K_1%  [RES0402_0-5]  24.74 78.52 270 bottom
R1033  10K_1%  [RES0402_0-5]  173.8 78.14 180 bottom
R1034  10K_1%  [RES0402_0-5]  16.75 78.06 180 bottom
R1035  0E  [RES0402_0-5]  178.25 78.05 180 bottom
R1036  10E_1%  [RES0402_0-5]  69.58 77.86 0 bottom
R1037  0E  [RES0201_0-5]  112.12 62.4 270 bottom
R1038  10K_1%  [RES0402_0-5]  16.75 76.92 180 bottom
R1039  0E  [RES0201_0-5]  113.03 62.4 270 bottom
R1040  240E_1%  [RES0201_0-5]  150.55 60.83 90 bottom
R1041  240E_1%  [RES0201_0-5]  151.54 60.88 90 bottom
R1042  10K_1%  [RES0402_0-5]  24.74 75.85 270 bottom
R1043  10K_1%  [RES0402_0-5]  16.75 75.78 0 bottom
R1044  0.01E_1%  [RES_FC4L16_0306-4_0-7]  166.56 75.65 270 bottom
R1045  0E  [RES0402_0-5]  84.08 75.43 270 bottom
R1046  0E  [RES0603_0-75]  98.87 74.96 0 bottom
R1047  10K_1%  [RES0402_0-5]  16.75 74.63 0 bottom
R1048  10E_1%  [RES0402_0-5]  69.57 74.42 0 bottom
R1049  0E  [RES0201_0-5]  115.36 63.5 270 bottom
R1050  0E  [RES0603_0-75]  98.87 73.69 0 bottom
R1051  0E  [RES0402_0-5]  84.08 73.6 90 bottom
R1052  0.01E_1%  [RES_FC4L16_0306-4_0-7]  166.56 73.44 270 bottom
R1053  10E_1%  [RES0402_0-5]  69.57 73.28 0 bottom
R1054  10K_1%  [RES0402_0-5]  159.58 67.21 270 bottom
R1055  10K  [RES0402_0-5]  22.01 72.18 0 bottom
R1056  10K  [RES0402_0-5]  20.16 72.18 0 bottom
R1057  0.01E_1%  [RES_FC4L16_0306-4_0-7]  185.99 71.77 90 bottom
R1058  0.01E_1%  [RES_FC4L16_0306-4_0-7]  166.58 71.23 270 bottom
R1059  0E  [RES0402_0-5]  17.79 71.09 0 bottom
R1060  0E  [RES0402_0-5]  16.95 71.09 180 bottom
R1061  0E  [RES0402_0-5]  198.66 70.9 0 bottom
R1062  10K_1%  [RES0402_0-5]  178.29 70.85 0 bottom
R1063  10K_1%  [RES0402_0-5]  176.39 70.8 180 bottom
R1064  10K_1%  [RES0402_0-5]  159.58 65.31 270 bottom
R1065  1K_1%  [RES0201_0-5]  54.41 70.7 270 bottom
R1066  1K_1%  [RES0201_0-5]  53.52 70.7 270 bottom
R1067  1K_1%  [RES0201_0-5]  52.63 70.7 270 bottom
R1068  1K_1%  [RES0201_0-5]  51.74 70.7 270 bottom
R1069  1K_1%  [RES0201_0-5]  50.85 70.7 270 bottom
R1070  1K_1%  [RES0201_0-5]  49.96 70.7 270 bottom
R1071  1K_1%  [RES0201_0-5]  49.07 70.7 270 bottom
R1072  10K_1%  [RES0402_0-5]  56.86 70.62 90 bottom
R1073  10K_1%  [RES0402_0-5]  55.59 70.62 270 bottom
R1074  1K_1%  [RES0201_0-5]  57.88 70.53 270 bottom
R1075  0E  [RES0402_0-5]  17.79 69.82 0 bottom
R1076  0E  [RES0402_0-5]  16.95 69.82 180 bottom
R1077  10K  [RES0402_0-5]  24.37 69.68 180 bottom
R1078  10K  [RES0402_0-5]  22.5 69.68 0 bottom
R1079  10K_1%  [RES0402_0-5]  198.66 69.63 180 bottom
R1080  1K_1%  [RES0402_0-5]  15.17 69.59 270 bottom
R1081  0E  [RES0402_0-5]  173.41 69.25 0 bottom
R1082  10E_1%  [RES0402_0-5]  240.12 69.12 90 bottom
R1083  10E_1%  [RES0402_0-5]  238.98 69.12 90 bottom
R1084  10E_1%  [RES0402_0-5]  69.58 68.91 0 bottom
R1085  0E  [RES0402_0-5]  17.79 68.55 0 bottom
R1086  0E  [RES0402_0-5]  16.95 68.55 180 bottom
R1087  10K  [RES0402_0-5]  24.37 68.54 180 bottom
R1088  10K  [RES0402_0-5]  22.5 68.54 0 bottom
R1089  1K_1%  [RES0402_0-5]  198.66 68.36 180 bottom
R1090  0E  [RES0603_0-75]  99.12 68.36 0 bottom
R1091  10E_1%  [RES0402_0-5]  69.58 67.77 0 bottom
R1092  0.01E_1%  [RES_FC4L16_0306-4_0-7]  80.89 67.67 270 bottom
R1093  0E  [RES0402_0-5]  17.79 67.28 0 bottom
R1094  0E  [RES0402_0-5]  16.95 67.28 180 bottom
R1095  10K  [RES0402_0-5]  23.31 66.93 0 bottom
R1096  0.01E_1%  [RES_FC4L16_0306-4_0-7]  166.14 66.93 0 bottom
R1097  0E  [RES0603_0-75]  96.19 66.63 0 bottom
R1098  1K_1%  [RES0201_0-5]  32.05 66.21 90 bottom
R1099  1K_1%  [RES0201_0-5]  31.03 66.21 90 bottom
R1100  3K_1%  [RES0402_0-5]  98.87 66.2 180 bottom
R1101  0E  [RES0402_0-5]  17.79 66.01 0 bottom
R1102  0E  [RES0402_0-5]  16.95 66.01 180 bottom
R1103  0E  [RES0402_0-5]  80.43 65.91 180 bottom
R1104  0E  [RES0402_0-5]  78.52 65.91 0 bottom
R1105  11K_1%  [RES0402_0-5]  98.87 65.18 0 bottom
R1106  10E_1%  [RES0402_0-5]  69.58 64.09 0 bottom
R1107  0E  [RES0402_0-5]  43.83 63.73 0 bottom
R1108  0E  [RES0402_0-5]  42.99 63.73 180 bottom
R1109  10K  [RES0402_0-5]  55.46 63.25 0 bottom
R1110  10E_1%  [RES0402_0-5]  69.58 62.94 0 bottom
R1111  0E  [RES0402_0-5]  198.77 60.72 0 bottom
R1112  0E  [RES0402_0-5]  43.83 62.46 0 bottom
R1113  0E  [RES0402_0-5]  42.99 62.46 180 bottom
R1114  1K_1%  [RES0201_0-5]  121.63 50.06 90 top
R1115  1K_1%  [RES0201_0-5]  122.6 50.06 90 top
R1116  1K_1%  [RES0201_0-5]  125.63 50.06 90 top
R1117  1K_1%  [RES0201_0-5]  126.6 50.06 90 top
R1118  10K_1%  [RES0201_0-5]  124.63 50.06 270 top
R1119  0E  [RES0402_0-5]  128.4 49.96 270 top
R1120  10K_1%  [RES0402_0-5]  157.41 68.61 270 bottom
R1121  10K_1%  [RES0402_0-5]  159.6 71.2 270 bottom
R1122  10K_1%  [RES0402_0-5]  200.55 61.57 90 bottom
R1123  0E  [RES0402_0-5]  198.77 61.99 0 bottom
R1124  10K  [RES0402_0-5]  139.61 53.01 90 top
R1125  10K  [RES0402_0-5]  138.34 53.01 90 top
R1126  10K  [RES0402_0-5]  137.07 53.01 90 top
R1127  10K_1%  [RES0402_0-5]  159.6 69.29 270 bottom
R1128  0E  [RES0402_0-5]  23.58 59.13 270 bottom
R1129  0E  [RES0402_0-5]  22.4 59.13 270 bottom
R1130  10K  [RES0402_0-5]  134.07 46.73 180 top
R1131  10K  [RES0402_0-5]  204.4 58.24 90 bottom
R1132  10K  [RES0402_0-5]  57.95 58.13 90 bottom
R1133  10K  [RES0402_0-5]  143.49 47.19 0 top
R1134  10K  [RES0402_0-5]  187.89 57.46 0 bottom
R1135  10K  [RES0402_0-5]  56.85 54.93 0 bottom
R1136  10K_1%  [RES0201_0-5]  71.99 54.29 90 bottom
R1137  1K_1%  [RES0201_0-5]  64.23 53.63 180 bottom
R1138  1K_1%  [RES0201_0-5]  64.23 52.69 180 bottom
R1139  0E  [RES0402_0-5]  71.97 52.05 90 bottom
R1140  0E  [RES0402_0-5]  70.93 52.05 270 bottom
R1141  10K_1%  [RES0201_0-5]  69.91 52.05 90 bottom
R1142  1K_1%  [RES0201_0-5]  64.23 51.75 180 bottom
R1143  2.2K  [RES0201_0-5]  207.86 51.43 180 bottom
R1144  10K  [RES0402_0-5]  54.31 51.3 180 bottom
R1145  1K_1%  [RES0201_0-5]  64.23 50.81 180 bottom
R1147  2.2K  [RES0201_0-5]  207.86 50.42 180 bottom
R1149  2.2K  [RES0201_0-5]  191.17 49.74 270 bottom
R1150  2.2K  [RES0201_0-5]  190.15 49.74 270 bottom
R1151  10K  [RES0402_0-5]  192.26 49.66 270 bottom
R1153  0E  [RES0402_0-5]  19.35 49.4 180 bottom
R1155  0E  [RES0402_0-5]  19.35 48.26 180 bottom
R1156  4.7K  [RES0402_0-5]  29.02 48.11 180 bottom
R1157  0E  [RES0402_0-5]  27.33 47.69 270 bottom
R1158  10K_1%  [RES0201_0-5]  73.08 47.1 90 bottom
R1159  0E  [RES0402_0-5]  72.07 47.1 270 bottom
R1160  0E  [RES0402_0-5]  70.93 47.1 270 bottom
R1161  10K  [RES0402_0-5]  29.02 46.97 0 bottom
R1162  10K_1%  [RES0201_0-5]  70.93 45.32 270 bottom
R1168  0E  [RES0402_0-5]  31.3 42.27 0 bottom
R1170  10K  [RES0402_0-5]  52.94 42.07 0 bottom
R1171  0E  [RES0402_0-5]  31.3 41.13 0 bottom
R1172  0E  [RES0402_0-5]  52.94 40.8 180 bottom
R1177  0E  [RES0402_0-5]  31.3 39.99 0 bottom
R1178  10K  [RES0402_0-5]  194.51 39.87 180 bottom
R1179  10K  [RES0402_0-5]  190.24 39.87 0 bottom
R1180  0E  [RES0402_0-5]  46.03 39.85 0 bottom
R1181  0E  [RES0402_0-5]  52.94 39.66 180 bottom
R1182  10K  [RES0402_0-5]  192.95 39.45 90 bottom
R1183  10K  [RES0402_0-5]  191.8 39.45 90 bottom
R1184  10K  [RES0402_0-5]  46.03 38.71 180 bottom
R1185  0E  [RES0402_0-5]  52.94 38.51 180 bottom
R1186  1K_1%  [RES0402_0-5]  21.59 37.62 0 bottom
R1187  0E  [RES0402_0-5]  83.13 35.14 270 bottom
R1188  1K_1%  [RES0402_0-5]  21.59 35.08 0 bottom
R1189  10K  [RES0402_0-5]  23.25 35.08 270 bottom
R1190  0E  [RES0402_0-5]  164.67 34.75 270 bottom
R1191  0E  [RES0402_0-5]  163.52 34.75 270 bottom
R1192  0E  [RES0402_0-5]  162.38 34.75 270 bottom
R1193  0E  [RES0402_0-5]  161.24 34.75 270 bottom
R1194  1M_1%  [RES0402_0-5]  84.72 34.72 0 bottom
R1195  10K  [RES0402_0-5]  22.65 33.45 180 bottom
R1196  100K  [RES0402_0-5]  186.17 32.73 270 bottom
R1197  2.49K_1%  [RES0402_0-5]  102.73 32.62 90 bottom
R1198  2.49K_1%  [RES0402_0-5]  100.61 32.62 90 bottom
R1199  2.49K_1%  [RES0402_0-5]  77.07 32.62 90 bottom
R1200  2.49K_1%  [RES0402_0-5]  74.96 32.62 90 bottom
R1201  0E  [RES0201_0-5]  76.01 32.53 270 bottom
R1202  0E  [RES0201_0-5]  73.82 32.53 270 bottom
R1203  0E  [RES0201_0-5]  101.66 32.53 270 bottom
R1204  0E  [RES0201_0-5]  99.47 32.53 270 bottom
R1205  0E  [RES0201_0-5]  79.22 31.45 270 bottom
R1206  0E  [RES0201_0-5]  104.87 31.45 270 bottom
R1207  10K  [RES0402_0-5]  85.66 31.32 270 bottom
R1208  10K  [RES0402_0-5]  87.08 30.84 270 bottom
R1209  0E  [RES0201_0-5]  103.79 30.79 270 bottom
R1210  0E  [RES0201_0-5]  101.66 30.79 270 bottom
R1211  0E  [RES0201_0-5]  99.53 30.79 270 bottom
R1212  0E  [RES0201_0-5]  78.14 30.79 270 bottom
R1213  0E  [RES0201_0-5]  76.01 30.79 270 bottom
R1214  0E  [RES0201_0-5]  73.87 30.79 270 bottom
R1215  10K_1%  [RES0402_0-5]  102.73 30.77 270 bottom
R1216  10K_1%  [RES0402_0-5]  100.61 30.77 270 bottom
R1217  10K_1%  [RES0402_0-5]  77.07 30.77 270 bottom
R1218  10K_1%  [RES0402_0-5]  74.96 30.77 270 bottom
R1219  7.5K  [RES0402_0-5]  29.51 30.76 0 bottom
R1220  5.76K_1%  [RES0402_0-5]  105.29 30.06 180 bottom
R1221  5.76K_1%  [RES0402_0-5]  79.64 30.06 180 bottom
R1222  7.5K  [RES0402_0-5]  29.51 29.62 0 bottom
R1223  2.49K_1%  [RES0402_0-5]  105.29 28.91 0 bottom
R1224  2.49K_1%  [RES0402_0-5]  79.64 28.91 0 bottom
R1225  10K  [RES0402_0-5]  58.36 28.88 180 bottom
R1226  3.74K_1%  [RES0402_0-5]  26.65 28.47 0 bottom
R1227  100K  [RES0402_0-5]  219.47 28.28 180 bottom
R1228  100K  [RES0402_0-5]  217.27 28.23 0 bottom
R1229  10K  [RES0402_0-5]  30.76 27.88 90 bottom
R1230  10K  [RES0402_0-5]  29.49 27.88 270 bottom
R1231  2.49K_1%  [RES0402_0-5]  105.29 27.77 0 bottom
R1232  2.49K_1%  [RES0402_0-5]  79.64 27.77 0 bottom
R1233  1K_1%  [RES0402_0-5]  179.48 27.34 270 bottom
R1234  5.76K_1%  [RES0402_0-5]  105.29 26.63 180 bottom
R1235  5.76K_1%  [RES0402_0-5]  79.64 26.63 180 bottom
R1236  1.5K_1%  [RES0402_0-5]  29.07 26.38 0 bottom
R1237  5.6K_1%  [RES0402_0-5]  24.55 26.31 180 bottom
R1238  360E_1%  [RES0402_0-5]  27.22 25.72 90 bottom
R1239  360E_1%  [RES0402_0-5]  26.08 25.72 90 bottom
R1240  0E  [RES0402_0-5]  180.63 25.43 90 bottom
R1241  0E  [RES0402_0-5]  179.48 25.43 90 bottom
R1242  10K  [RES0402_0-5]  61.78 24.85 270 bottom
R1243  10K_1%  [RES0402_0-5]  229.12 24.76 90 bottom
R1244  1.69K_1%  [RES0402_0-5]  86.32 24.67 0 bottom
R1245  2.2K  [RES0402_0-5]  79.64 24.27 0 bottom
R1246  2.2K  [RES0402_0-5]  105.29 24.27 0 bottom
R1247  0E  [RES0201_0-5]  212.71 24.24 180 bottom
R1248  3.57K_1%  [RES0402_0-5]  86.06 23.15 90 bottom
R1249  10K_1%  [RES0402_0-5]  79.64 23.13 180 bottom
R1250  10K_1%  [RES0402_0-5]  105.29 23.13 180 bottom
R1251  0E  [RES0201_0-5]  212.63 22.79 180 bottom
R1252  47K_1%  [RES0402_0-5]  15.85 22.14 270 bottom
R1253  2.49K_1%  [RES0402_0-5]  105.29 22.11 0 bottom
R1254  2.49K_1%  [RES0402_0-5]  79.64 22.11 0 bottom
R1255  2.49K_1%  [RES0402_0-5]  105.29 20.97 0 bottom
R1256  2.49K_1%  [RES0402_0-5]  79.64 20.97 0 bottom
R1257  100K  [RES0402_0-5]  188.42 20.5 270 bottom
R1258  11K_1%  [RES0402_0-5]  95.32 20.24 0 bottom
R1259  11K_1%  [RES0402_0-5]  69.67 20.24 0 bottom
R1260  10K_1%  [RES0402_0-5]  105.29 19.82 180 bottom
R1261  10K_1%  [RES0402_0-5]  79.64 19.82 180 bottom
R1262  100K  [RES0402_0-5]  213.07 19.77 0 bottom
R1263  47K_1%  [RES0402_0-5]  15.85 19.3 90 bottom
R1264  4.99K_1%  [RES0402_0-5]  61.02 18.75 0 bottom
R1265  1.87K_1%  [RES0402_0-5]  60.77 17.23 90 bottom
R1266  10K  [RES0402_0-5]  206.61 16.32 0 bottom
R1267  10K  [RES0402_0-5]  117.55 16.06 0 bottom
R1268  2.2K  [RES0402_0-5]  204.92 15.9 270 bottom
R1269  10K  [RES0402_0-5]  203.26 15.9 90 bottom
R1270  10K  [RES0402_0-5]  201.99 15.9 90 bottom
R1271  360E_1%  [RES0402_0-5]  28.41 15.77 270 bottom
R1272  360E_1%  [RES0402_0-5]  27.27 15.77 270 bottom
R1273  10K  [RES0402_0-5]  32.84 15.53 270 bottom
R1274  10K  [RES0402_0-5]  31.66 15.53 90 bottom
R1275  1.5K_1%  [RES0402_0-5]  30.07 15.11 0 bottom
R1276  5.6K_1%  [RES0402_0-5]  25.62 15.11 180 bottom
R1277  10K_1%  [RES0402_0-5]  229.55 14.49 270 bottom
R1278  10K_1%  [RES0402_0-5]  227.6 14.49 270 bottom
R1279  3.74K_1%  [RES0402_0-5]  27.84 13.02 0 bottom
R1280  2.2K  [RES0201_0-5]  54.74 12.16 90 bottom
R1281  2.2K  [RES0201_0-5]  53.72 12.16 90 bottom
R1282  7.5K  [RES0402_0-5]  28.41 10.93 270 bottom
R1283  7.5K  [RES0402_0-5]  27.27 10.93 270 bottom
R1284  0E  [RES0402_0-5]  199.5 7.58 90 bottom
R1285  0E  [RES0402_0-5]  222.1 7.1 90 bottom
R1286  220E_1%  [RES0402_0-5]  109.87 5.34 0 bottom
R1287  220E_1%  [RES0402_0-5]  91.09 5.34 180 bottom
R1288  220E_1%  [RES0402_0-5]  84.21 5.34 0 bottom
R1289  220E_1%  [RES0402_0-5]  65.44 5.34 180 bottom
R1290  220E_1%  [RES0402_0-5]  91.09 3.31 180 bottom
R1291  220E_1%  [RES0402_0-5]  65.44 3.31 180 bottom
R1292  10K_1%  [RES0201_0-5]  57.04 104.59 270 top
R1294  0E  [RES0402_0-5]  85.18 78.22 270 bottom
R1295  56.2K_1%  [RES0402_0-5]  83.43 82.96 90 top
R1296  10K_1%  [RES0402_0-5]  86.52 79.1 90 bottom
R1297  24.9K_1%  [RES0402_0-5]  83.4 81.21 90 top
R1298  0E  [RES0402_0-5]  111.09 119.4 0 top
R1299  0E  [RES0402_0-5]  72.54 75.33 90 top
R1300  0E  [RES0402_0-5]  163.21 50.01 90 top
R1301  10K_1%  [RES0402_0-5]  129.07 23.28 0 bottom
R1302  0E  [RES0402_0-5]  128.23 22.01 0 bottom
R1303  0E  [RES0402_0-5]  11.38 137.36 270 top
R1304  0E  [RES0402_0-5]  10.07 137.36 270 top
R1305  10K  [RES0402_0-5]  201.83 53.77 270 top
R1308  0E  [RES0402_0-5]  206.31 101.09 270 top
R1309  10K_1%  [RES0402_0-5]  78.42 69.47 180 top
R1310  10K_1%  [RES0402_0-5]  155.76 48.62 90 top
R1311  0E  [RES0402_0-5]  59.42 69.57 180 bottom
R1312  0E  [RES0402_0-5]  196.86 39.55 0 top
R1313  0E  [RES0402_0-5]  59.65 89.71 180 bottom
R1314  0E  [RES0402_0-5]  197.85 85.37 0 bottom
R1315  0E  [RES0603_0-75]  186.65 40.13 180 top
R1316  0E  [RES0603_0-75]  69.25 65.84 270 bottom
R1317  0E  [RES0603_0-75]  186.57 48.67 180 top
R1318  0E  [RES0603_0-75]  186.7 44.22 180 top
SW1  1101M2S3CQE2  [SW3_185_500X260_TH_13]  239.95 180.03 270 top
SW2  218-10LPST  [SW10_50_550X230_SMD]  148.44 164.42 180 top
SW3  7914G-1-000E  [SW4_100X216_200X200_SMD_4-2]  11.74 124.11 270 top
SW4  218-2LPST  [SW4_49-99_150X230_SMD_2-7]  12.63 113.06 90 top
SW5  7914G-1-000E  [SW4_100X216_200X200_SMD_4-2]  238.84 71.91 270 top
SW6  7914G-1-000E  [SW4_100X216_200X200_SMD_4-2]  238.84 64.8 270 top
SW7  218-8LPSTR  [SW8_218-8LPST_450X230_SMD_2-7]  52.58 63.74 90 top
SW8  7914G-1-000E  [SW4_100X216_200X200_SMD_4-2]  15.1 60.82 270 top
SW9  7914G-1-000E  [SW4_100X216_200X200_SMD_4-2]  238.84 57.69 270 top
SW10  7914G-1-000E  [SW4_100X216_200X200_SMD_4-2]  238.84 50.58 270 top
SW11  218-8LPSTR  [SW8_218-8LPST_450X230_SMD_2-7]  52.58 50.18 90 top
SW12  7914G-1-000E  [SW4_100X216_200X200_SMD_4-2]  238.84 43.47 270 top
SW13  218-2LPST  [SW4_49-99_150X230_SMD_2-7]  16.67 36.79 0 top
SW14  7914G-1-000E  [SW4_100X216_200X200_SMD_4-2]  238.84 36.35 270 top
SW15  7914G-1-000E  [SW4_100X216_200X200_SMD_4-2]  238.84 29.24 270 top
SW16  218-4LPST  [SW8_218-4LPS_230X250_SMD_2-7]  232.04 20.33 0 top
TP1  THRU HOLE  [TP_40X65]  181.02 186.82 0 top
TP2  -  [TP30_SMD]  17.71 183.51 270 top
TP3  -  [TP30_SMD]  15.17 183.04 0 top
TP4  -  [TP30_SMD]  176.72 182.61 180 top
TP5  -  [TP30_SMD]  14.58 180.66 0 top
TP7  -  [TP30_SMD]  20.95 174.52 0 top
TP8  -  [TP30_SMD]  22.38 174.51 0 top
TP10  THRU HOLE  [TP_40X65]  34.6 72.3 0 top
TP11  -  [TP30_SMD]  20.95 173.02 0 top
TP12  -  [TP30_SMD]  22.32 172.98 0 top
TP13  -  [TP30_SMD]  24.68 172.32 0 top
TP14  -  [TP40_SMD]  182.48 170.57 0 top
TP16  -  [TP40_SMD]  31.43 164.13 270 top
TP17  -  [TP40_SMD]  108.39 162.11 90 top
TP18  -  [TP40_SMD]  111.82 162.11 90 top
TP20  THRU HOLE  [TP_40X65]  212.02 158.12 270 top
TP21  THRU HOLE  [TP_40X65]  159.45 157.58 0 top
TP22  THRU HOLE  [TP_40X65]  161.99 157.58 0 top
TP23  -  [TP30_SMD]  209.28 155.18 270 top
TP24  -  [TP40_SMD]  107.55 154.24 90 top
TP26  -  [TP40_SMD]  13.32 151.44 0 top
TP27  THRU HOLE  [TP_40X65]  157.69 150.35 0 top
TP28  THRU HOLE  [TP_40X65]  60.23 134.6 0 top
TP30  -  [TP30_SMD]  184.51 88.74 0 top
TP31  THRU HOLE  [TP_40X65]  221.04 130.77 0 top
TP32  THRU HOLE  [TP_40X65]  201.25 130.33 270 top
TP33  -  [TP40_SMD]  65.12 129.85 0 top
TP34  -  [TP30_SMD]  203.22 128.88 90 top
TP35  -  [TP30_SMD]  204.63 128.88 90 top
TP36  THRU HOLE  [TP_40X65]  201.31 127.61 270 top
TP37  5002  [TP_CIR67D40_TH_4-6]  236.86 126.8 90 top
TP38  -  [TP30_SMD]  172.78 122.89 270 top
TP39  -  [TP30_SMD]  20.96 122.84 90 top
TP40  -  [TP40_SMD]  51.25 121.13 0 top
TP44  -  [TP20_SMD]  27.22 120.39 0 top
TP48  -  [TP40_SMD]  40.32 119.51 90 top
TP49  -  [TP40_SMD]  54.57 119.44 180 top
TP51  -  [TP30_SMD]  70.93 118.9 0 top
TP52  -  [TP30_SMD]  110.8 118.02 270 top
TP53  -  [TP20_SMD]  27.22 118.22 0 top
TP57  -  [TP20_SMD]  26.61 117.16 0 top
